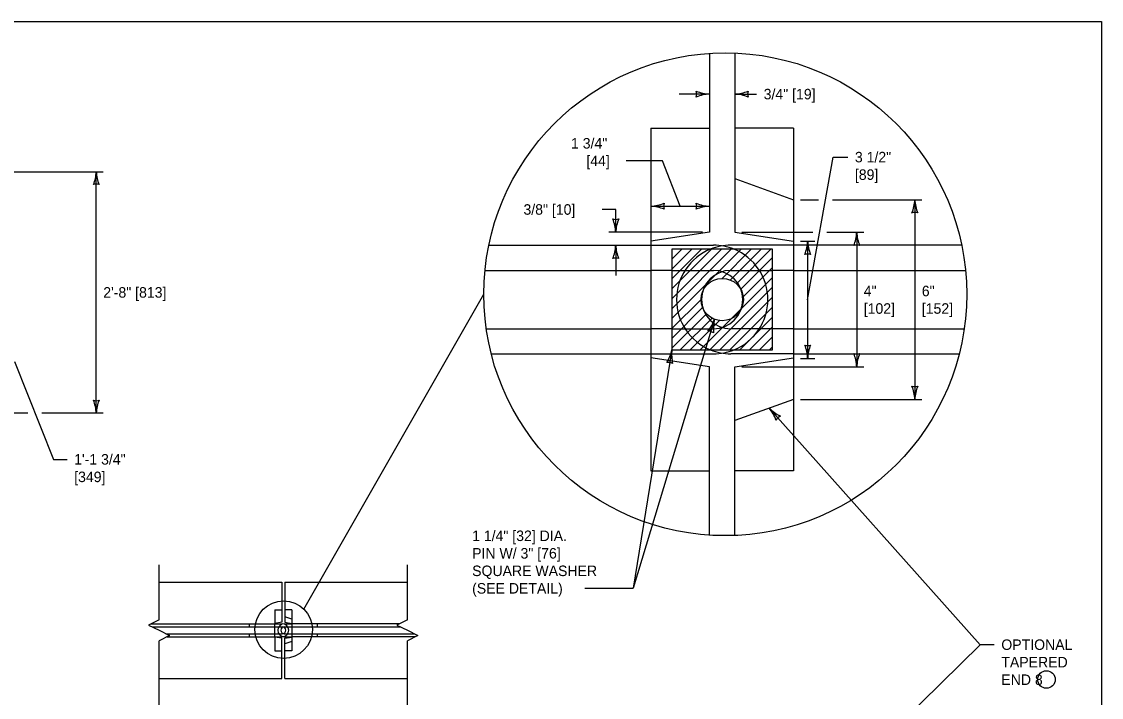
# Model space of a CAD drawing. Extents: x 49991.4 to 50021, y 49987.6 to 50011.4.
# Drawn here: x 50010.59 to 50016.75, y 49995.14 to 49999 of the extents above; entities that cross this region are included whole.
import ezdxf

# ---------------------------------------------------------------- set-up
doc = ezdxf.new("R2010")
doc.units = 0
for name, color, linetype in [('Level 1', 7, 'Continuous'), ('Level 2', 7, 'Continuous'), ('Level 3', 7, 'Continuous'), ('Level 4', 7, 'Continuous'), ('Level 6', 7, 'Continuous')]:
    doc.layers.add(name, color=color, linetype=linetype)

msp = doc.modelspace()

# ---------------------------------------------------------------- linework, layer by layer
at = {"layer": 'Level 1'}
for p, q in [((50014.5138, 49998.8183), (50014.5138, 49997.7965)), ((50014.6573, 49998.8201), (50014.6573, 49997.7965)), ((50014.6573, 49998.1025), (50014.9934, 49997.9825)), ((50014.9934, 49997.9825), (50014.9934, 49996.8421)), ((50014.5138, 49997.7965), (50014.1777, 49997.7449)), ((50014.6573, 49997.7965), (50014.9934, 49997.7449)), ((50014.1777, 49997.7449), (50014.1777, 49997.0797)), ((50014.1777, 49997.7223), (50014.5365, 49997.7223)), ((50014.9934, 49997.7223), (50014.6347, 49997.7223)), ((50014.8729, 49997.6995), (50014.2983, 49997.6995)), ((50014.2983, 49997.6995), (50014.2983, 49997.1251)), ((50014.2983, 49997.6429), (50014.3549, 49997.6995)), ((50014.2983, 49997.5864), (50014.4114, 49997.6995)), ((50014.2983, 49997.5298), (50014.468, 49997.6995)), ((50014.2983, 49997.4732), (50014.5246, 49997.6995)), ((50014.2983, 49997.4167), (50014.5811, 49997.6995)), ((50014.2983, 49997.3601), (50014.6377, 49997.6995)), ((50014.2983, 49997.3035), (50014.6943, 49997.6995)), ((50014.5847, 49997.5333), (50014.7508, 49997.6995)), ((50014.632, 49997.5241), (50014.8074, 49997.6995)), ((50014.6666, 49997.5022), (50014.864, 49997.6995)), ((50014.6916, 49997.4706), (50014.8729, 49997.6519)), ((50014.8729, 49997.1251), (50014.8729, 49997.6995)), ((50014.7055, 49997.4279), (50014.8729, 49997.5953)), ((50014.2983, 49997.5787), (50014.1777, 49997.5787)), ((50014.6371, 49997.3029), (50014.8729, 49997.5387)), ((50014.9934, 49997.5787), (50014.8729, 49997.5787)), ((50014.5158, 49997.1251), (50014.8729, 49997.4822)), ((50014.2983, 49997.247), (50014.4646, 49997.4133)), ((50014.5724, 49997.1251), (50014.8729, 49997.4256)), ((50014.2983, 49997.1904), (50014.4739, 49997.366)), ((50014.629, 49997.1251), (50014.8729, 49997.369)), ((50014.2983, 49997.1338), (50014.4958, 49997.3313)), ((50014.3461, 49997.1251), (50014.5274, 49997.3063)), ((50014.4027, 49997.1251), (50014.57, 49997.2924)), ((50014.4593, 49997.1251), (50014.6371, 49997.3029)), ((50014.6855, 49997.1251), (50014.8729, 49997.3125)), ((50014.2983, 49997.2459), (50014.1777, 49997.2459)), ((50014.7421, 49997.1251), (50014.8729, 49997.2559)), ((50014.9934, 49997.2459), (50014.8729, 49997.2459)), ((50014.7987, 49997.1251), (50014.8729, 49997.1993)), ((50014.1777, 49997.1024), (50014.5365, 49997.1024)), ((50014.2983, 49997.1251), (50014.8729, 49997.1251)), ((50014.9934, 49997.1024), (50014.6348, 49997.1024)), ((50014.8553, 49997.1251), (50014.8729, 49997.1427)), ((50014.5138, 49997.0284), (50014.1777, 49997.0797)), ((50014.6573, 49997.0284), (50014.9934, 49997.0797)), ((50014.5138, 49996.0671), (50014.5138, 49997.0284)), ((50014.6573, 49996.0653), (50014.6573, 49997.0284)), ((50014.9934, 49996.8421), (50014.6573, 49996.7221)), ((50011.371, 49995.7985), (50012.0713, 49995.7985)), ((50012.0713, 49995.7985), (50012.0713, 49995.5698)), ((50012.0884, 49995.7985), (50012.7886, 49995.7985)), ((50012.0884, 49995.7985), (50012.0885, 49995.5698)), ((50012.0713, 49995.5698), (50012.0314, 49995.5636)), ((50012.0314, 49995.4844), (50012.0314, 49995.5636)), ((50012.0314, 49995.561), (50012.0741, 49995.561)), ((50012.0858, 49995.5609), (50012.1285, 49995.5609)), ((50012.1285, 49995.5873), (50012.0885, 49995.6006)), ((50012.0885, 49995.5698), (50012.1285, 49995.5636)), ((50012.1285, 49995.5873), (50012.1285, 49995.4607)), ((50012.0314, 49995.5438), (50012.0741, 49995.5438)), ((50012.0314, 49995.5042), (50012.0741, 49995.5042)), ((50012.0858, 49995.5438), (50012.1285, 49995.5438)), ((50012.0858, 49995.5042), (50012.1285, 49995.5042)), ((50012.0314, 49995.4871), (50012.0741, 49995.4871)), ((50012.0713, 49995.4783), (50012.0314, 49995.4844)), ((50012.0713, 49995.2495), (50012.0713, 49995.4783)), ((50012.0858, 49995.4871), (50012.1285, 49995.4871)), ((50012.0884, 49995.2495), (50012.0885, 49995.4783)), ((50012.0885, 49995.4783), (50012.1285, 49995.4844)), ((50012.1285, 49995.4607), (50012.0885, 49995.4474)), ((50011.371, 49995.2495), (50012.0713, 49995.2495)), ((50012.0884, 49995.2495), (50012.7886, 49995.2495))]:
    msp.add_line(p, q, dxfattribs=at)
msp.add_lwpolyline([(49999.3835, 49998.9992), (50016.7501, 49998.9992), (50016.7501, 49987.7988), (49999.3835, 49987.7988)], close=True, dxfattribs=at)
msp.add_circle((50014.5856, 49997.4123), 0.121, dxfattribs=at)
for centre, radius, start, end in [((50014.6348, 49997.4123), 0.31, 90, 112.10261), ((50014.5365, 49997.4123), 0.31, 67.89739, 90), ((50014.6348, 49997.4123), 0.31, 247.9226, 270), ((50014.5365, 49997.4123), 0.31, 270, 292.0774), ((50012.0858, 49995.524), 0.0369, 90, 270), ((50012.0741, 49995.524), 0.037, 270, 90), ((50012.0858, 49995.524), 0.0198, 90, 270), ((50012.0741, 49995.524), 0.0198, 270, 89.99999)]:
    msp.add_arc(centre, radius, start, end, dxfattribs=at)
at = {"layer": 'Level 2'}
msp.add_circle((50016.4363, 49995.2431), 0.05, dxfattribs=at)
at = {"layer": 'Level 3'}
for p, q in [((50014.5138, 49998.5853), (50014.3404, 49998.5853)), ((50014.6573, 49998.5852), (50014.7823, 49998.5852)), ((50009.893, 49998.1415), (50011.0526, 49998.1415)), ((50011.0126, 49996.7646), (50011.0126, 49998.1414)), ((50015.0334, 49997.9825), (50015.1355, 49997.9825)), ((50015.2155, 49997.9825), (50015.725, 49997.9825)), ((50015.685, 49997.9825), (50015.685, 49996.8421)), ((50013.9778, 49997.9265), (50013.8998, 49997.9265)), ((50013.9778, 49997.7965), (50013.9778, 49997.9265)), ((50014.1777, 49997.945), (50014.5138, 49997.945)), ((50014.4738, 49997.7965), (50013.9378, 49997.7965)), ((50014.6973, 49997.7965), (50015.1023, 49997.7965)), ((50015.1823, 49997.7965), (50015.3935, 49997.7965)), ((50015.3535, 49997.7965), (50015.3535, 49997.0284)), ((50013.9778, 49997.7223), (50013.9778, 49997.5488)), ((50015.0334, 49997.7457), (50015.1134, 49997.7457)), ((50015.0734, 49997.7457), (50015.0734, 49997.0764)), ((50012.198, 49995.6436), (50013.2246, 49997.4427)), ((50014.5421, 49997.2994), (50014.0768, 49995.7635)), ((50014.2983, 49997.1251), (50014.0768, 49995.7635)), ((50015.0334, 49997.0764), (50015.1134, 49997.0764)), ((50014.6973, 49997.0284), (50015.3935, 49997.0284)), ((50016.0589, 49995.4418), (50014.8543, 49996.7925)), ((50015.0334, 49996.8421), (50015.725, 49996.8421)), ((50010.3169, 49996.7646), (50010.6227, 49996.7646)), ((50010.7027, 49996.7646), (50011.0526, 49996.7646)), ((50013.802, 49995.7635), (50014.0768, 49995.7635)), ((50016.0589, 49995.4418), (50015.1836, 49994.5845)), ((50016.1389, 49995.4418), (50016.0589, 49995.4418))]:
    msp.add_line(p, q, dxfattribs=at)
for points in [[(50014.3458, 49997.945), (50014.2443, 49998.2042), (50014.0367, 49998.2042)], [(50015.0734, 49997.411), (50015.2189, 49998.2255), (50015.3031, 49998.2255)], [(50010.5458, 49997.0591), (50010.7677, 49996.4999), (50010.8466, 49996.4999)]]:
    msp.add_lwpolyline(points, dxfattribs=at)
for centre, radius in [((50014.6031, 49997.4427), 1.3785), ((50012.082, 49995.5276), 0.1641)]:
    msp.add_circle(centre, radius, dxfattribs=at)
for centre, radius, start, end in [((50014.523, 49998.8074), 0.2223, 247.45601, 267.63952), ((50014.3856, 49998.5853), 0.0548, 342.13882, 17.86118), ((50014.5253, 49998.3526), 0.233, 92.82731, 112.07716), ((50014.6458, 49998.8179), 0.233, 272.82731, 292.07716), ((50014.6481, 49998.3631), 0.2223, 67.45601, 87.63952), ((50014.7855, 49998.5852), 0.0548, 162.13882, 197.86118), ((50010.7999, 49998.1501), 0.2128, 337.45601, 357.63952), ((50011.2354, 49998.1524), 0.2231, 182.82731, 202.07716), ((50011.0126, 49998.0186), 0.0524, 72.13882, 107.86118), ((50014.1662, 49998.1777), 0.233, 272.82731, 292.07716), ((50014.3059, 49997.945), 0.0548, 162.13882, 197.86118), ((50014.523, 49998.1672), 0.2223, 247.45601, 267.63952), ((50014.3856, 49997.945), 0.0548, 342.13882, 17.86118), ((50015.4629, 49997.9916), 0.2223, 337.45601, 357.63952), ((50015.9177, 49997.994), 0.233, 182.82731, 202.07716), ((50014.1685, 49997.7229), 0.2223, 67.45601, 87.63952), ((50014.5253, 49997.7123), 0.233, 92.82731, 112.07716), ((50015.685, 49997.8543), 0.0548, 72.13882, 107.86118), ((50013.9778, 49997.9247), 0.0548, 252.13882, 287.86118), ((50013.7451, 49997.785), 0.233, 2.82731, 22.07716), ((50014.2, 49997.7873), 0.2223, 157.45601, 177.63952), ((50015.1314, 49997.8056), 0.2223, 337.45601, 357.63952), ((50015.5862, 49997.8079), 0.233, 182.82731, 202.07716), ((50013.7557, 49997.7314), 0.2223, 337.45601, 357.63952), ((50014.2105, 49997.7337), 0.233, 182.82731, 202.07716), ((50014.8513, 49997.7548), 0.2223, 337.45601, 357.63952), ((50015.3061, 49997.7572), 0.233, 182.82731, 202.07716), ((50015.3535, 49997.6682), 0.0548, 72.13882, 107.86118), ((50013.9778, 49997.594), 0.0548, 72.13882, 107.86118), ((50015.0734, 49997.6174), 0.0548, 72.13882, 107.86118), ((50014.3322, 49997.3726), 0.2223, 320.60238, 340.78589), ((50014.7681, 49997.243), 0.233, 165.97368, 185.22353), ((50014.5049, 49997.1767), 0.0548, 55.28519, 91.00755), ((50014.0805, 49997.1698), 0.2223, 328.21619, 348.3997), ((50014.5298, 49997.0991), 0.233, 173.58749, 192.83734), ((50015.0734, 49997.2046), 0.0548, 252.13882, 287.86118), ((50014.8407, 49997.0649), 0.233, 2.82731, 22.07716), ((50015.2956, 49997.0673), 0.2223, 157.45601, 177.63952), ((50015.3535, 49997.1566), 0.0548, 252.13882, 287.86118), ((50015.1208, 49997.0169), 0.233, 2.82731, 22.07716), ((50015.5756, 49997.0192), 0.2223, 157.45601, 177.63952), ((50014.2777, 49996.9985), 0.0548, 62.899, 98.62136), ((50015.685, 49996.9703), 0.0548, 252.13882, 287.86118), ((50015.4523, 49996.8306), 0.233, 2.82731, 22.07716), ((50015.9071, 49996.833), 0.2223, 157.45601, 177.63952), ((50011.0126, 49996.8873), 0.0524, 252.13882, 287.86118), ((50010.7898, 49996.7536), 0.2231, 2.82731, 22.07716), ((50011.2253, 49996.7558), 0.2128, 157.45601, 177.63952), ((50014.6824, 49996.6514), 0.2223, 19.18469, 39.3682), ((50015.0203, 49996.9559), 0.233, 224.55599, 243.80584), ((50014.9396, 49996.6968), 0.0548, 113.8675, 149.58986)]:
    msp.add_arc(centre, radius, start, end, dxfattribs=at)
at = {"layer": 'Level 4'}
for p, q in [((50014.1777, 49998.3913), (50014.5138, 49998.3913)), ((50014.1777, 49998.3913), (50014.1777, 49997.7449)), ((50014.9934, 49998.3913), (50014.6573, 49998.3913)), ((50014.9934, 49998.3913), (50014.9934, 49997.9825)), ((50013.2532, 49997.7223), (50014.1777, 49997.7223)), ((50015.9529, 49997.7223), (50014.9934, 49997.7223)), ((50013.2313, 49997.5787), (50014.1777, 49997.5787)), ((50014.2983, 49997.5787), (50014.5366, 49997.5787)), ((50014.6347, 49997.5787), (50014.8729, 49997.5787)), ((50014.9934, 49997.5787), (50015.9748, 49997.5787)), ((50013.2387, 49997.2459), (50014.1777, 49997.2459)), ((50014.2983, 49997.2459), (50014.5366, 49997.2459)), ((50014.8729, 49997.2459), (50014.6347, 49997.2459)), ((50014.9934, 49997.2459), (50015.9674, 49997.2459)), ((50013.2673, 49997.1024), (50014.1777, 49997.1024)), ((50014.9934, 49997.1024), (50015.9388, 49997.1024)), ((50014.1777, 49997.0797), (50014.1777, 49996.4335)), ((50014.9934, 49996.8421), (50014.9934, 49996.4335)), ((50014.1777, 49996.4335), (50014.5138, 49996.4335)), ((50014.9934, 49996.4335), (50014.6573, 49996.4335)), ((50012.0314, 49995.6406), (50012.0713, 49995.6406)), ((50012.0314, 49995.6406), (50012.0314, 49995.5636)), ((50012.1285, 49995.6406), (50012.0885, 49995.6406)), ((50012.1285, 49995.6406), (50012.1285, 49995.5873)), ((50011.3249, 49995.561), (50012.0314, 49995.561)), ((50011.8868, 49995.5438), (50011.8868, 49995.561)), ((50012.7423, 49995.5609), (50012.1285, 49995.5609)), ((50012.2756, 49995.5438), (50012.2756, 49995.5609)), ((50011.3315, 49995.5438), (50012.0314, 49995.5438)), ((50011.4107, 49995.5042), (50012.0314, 49995.5042)), ((50011.8868, 49995.4871), (50011.8868, 49995.5042)), ((50012.1285, 49995.5438), (50012.7491, 49995.5438)), ((50012.1285, 49995.5042), (50012.8283, 49995.5042)), ((50012.2756, 49995.4871), (50012.2756, 49995.5042)), ((50011.4171, 49995.4871), (50012.0314, 49995.4871)), ((50012.0314, 49995.4844), (50012.0314, 49995.4075)), ((50012.8347, 49995.4871), (50012.1285, 49995.4871)), ((50012.1285, 49995.4607), (50012.1285, 49995.4075)), ((50012.0314, 49995.4075), (50012.0713, 49995.4075)), ((50012.1285, 49995.4075), (50012.0885, 49995.4075))]:
    msp.add_line(p, q, dxfattribs=at)
for centre, radius, start, end in [((50014.6348, 49997.4123), 0.31, 112.10261, 247.9226), ((50014.5365, 49997.4123), 0.31, 292.0774, 67.89739), ((50014.6347, 49997.4123), 0.1664, 90, 270), ((50014.5366, 49997.4123), 0.1664, 270, 90)]:
    msp.add_arc(centre, radius, start, end, dxfattribs=at)
at = {"layer": 'Level 6'}
for p, q in [((50011.371, 49995.584), (50011.371, 49995.8985)), ((50012.7886, 49995.584), (50012.7886, 49995.8985)), ((50011.371, 49995.584), (50011.311, 49995.554)), ((50011.311, 49995.554), (50011.371, 49995.524)), ((50012.7886, 49995.584), (50012.7286, 49995.554)), ((50012.7286, 49995.554), (50012.7886, 49995.524)), ((50011.371, 49995.524), (50011.431, 49995.494)), ((50011.431, 49995.494), (50011.371, 49995.464)), ((50012.7886, 49995.524), (50012.8486, 49995.494)), ((50012.8486, 49995.494), (50012.7886, 49995.464)), ((50011.371, 49994.5538), (50011.371, 49995.464)), ((50012.7886, 49994.5538), (50012.7886, 49995.464))]:
    msp.add_line(p, q, dxfattribs=at)

# ---------------------------------------------------------------- texts
at = {"layer": 'Level 2'}
for s, p in [('3/4" [19]', (50014.8223, 49998.5552)), ('1 3/4"', (50013.7226, 49998.2742)), ('[44]', (50013.8102, 49998.1742)), ('3 1/2"', (50015.3431, 49998.1955)), ('[89]', (50015.3431, 49998.0955)), ('3/8" [10]', (50013.4512, 49997.8965)), ('2\'-8" [813]', (50011.0526, 49997.423)), ('4"', (50015.3935, 49997.4311)), ('6"', (50015.725, 49997.4311)), ('[102]', (50015.3935, 49997.3311)), ('[152]', (50015.725, 49997.3311)), ('1\'-1 3/4"', (50010.8866, 49996.4699)), ('[349]', (50010.8866, 49996.3699)), ('1 1/4" [32] DIA.', (50013.1582, 49996.0335)), ('PIN W/ 3" [76]', (50013.1582, 49995.9335)), ('SQUARE WASHER', (50013.1582, 49995.8335)), ('(SEE DETAIL)', (50013.1582, 49995.7335)), ('OPTIONAL', (50016.1789, 49995.4118)), ('TAPERED ', (50016.1789, 49995.3118)), ('END 8', (50016.1789, 49995.2118))]:
    msp.add_text(s, height=0.06, dxfattribs=at).set_placement(p)

doc.saveas('drawing.dxf')
